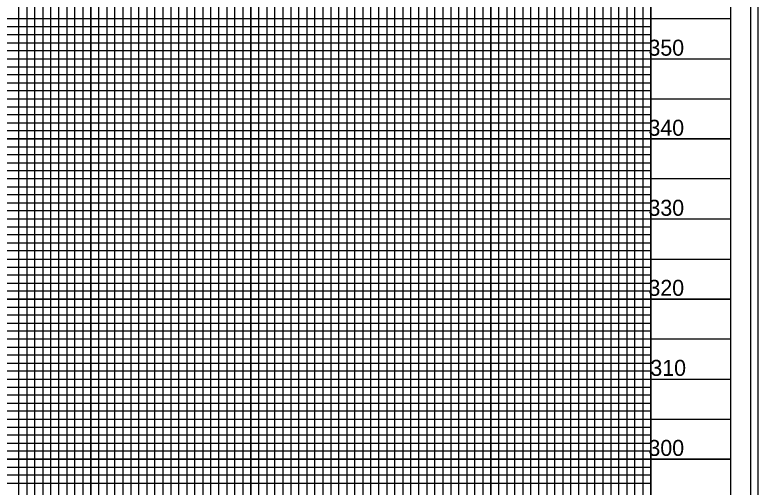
# Model space of a CAD drawing. Extents: x 10033 to 11717, y 9950 to 11050.
# Drawn here: x 11252.5 to 11717, y 10532.5 to 10827.5 of the extents above; entities that cross this region are included whole.
import ezdxf

# ---------------------------------------------------------------- set-up
doc = ezdxf.new("R2010")
doc.units = 0
for name, color, linetype in [('Exist Vertical Profile Vertical Axis Label', 7, 'Continuous'), ('Sheet DOT Grid CELL', 7, 'Continuous'), ('Sheet Layout Profile Border', 7, 'Continuous'), ('Sheet Plot Border Inside CELL', 7, 'Continuous'), ('Sheet Plot Border Outside CELL', 7, 'Continuous'), ('Sheet Profile CELL', 7, 'Continuous'), ('Sheet Profile Grid Major CELL', 7, 'Continuous'), ('Sheet Profile Grid Middle CELL', 7, 'Continuous'), ('Sheet Profile Grid Minor CELL', 7, 'Continuous')]:
    doc.layers.add(name, color=color, linetype=linetype)

msp = doc.modelspace()

# ---------------------------------------------------------------- linework, layer by layer
at = {"layer": 'Sheet DOT Grid CELL'}
for p, q in [((11300, 11025), (11300, 10000)), ((11350, 11025), (11350, 10000)), ((11400, 11025), (11400, 10000)), ((11450, 11025), (11450, 10000)), ((11500, 10000), (11500, 10887.45)), ((11550, 10000), (11550, 10887.45)), ((11600, 10000), (11600, 10887.45)), ((11650, 10000), (11650, 10887.45)), ((10200, 10800), (11700, 10800)), ((10200, 10750), (11700, 10750)), ((10200, 10700), (11700, 10700)), ((10200, 10650), (11700, 10650)), ((10200, 10600), (11700, 10600)), ((10200, 10550), (11700, 10550))]:
    msp.add_line(p, q, dxfattribs=at)
at = {"layer": 'Sheet Layout Profile Border'}
msp.add_lwpolyline([(10250, 11025), (10250, 10000), (11650, 10000), (11650, 10887.45), (11499.95, 10887.45), (11499.95, 11025)], close=True, dxfattribs=at)
at = {"layer": 'Sheet Plot Border Inside CELL'}
msp.add_lwpolyline([(11712.5, 11027.55), (10046, 11027.55), (10046, 9972.45), (11712.5, 9972.45)], close=True, dxfattribs=at)
at = {"layer": 'Sheet Plot Border Outside CELL'}
msp.add_lwpolyline([(11717, 11050), (10033, 11050), (10033, 9950), (11717, 9950)], close=True, dxfattribs=at)
at = {"layer": 'Sheet Profile CELL'}
msp.add_lwpolyline([(11700, 11025), (10200, 11025), (10200, 9975), (11700, 9975)], close=True, dxfattribs=at)
at = {"layer": 'Sheet Profile Grid Major CELL'}
for points in [[(11300, 10000), (11300, 11025), (11350, 11025), (11350, 10000)], [(11400, 10000), (11400, 11025), (11450, 11025), (11450, 10000)], [(11500, 10000), (11500, 11025), (11526.3, 11025)], [(11550, 10887.45), (11550, 10000), (11600, 10000), (11600, 10887.45)], [(11650, 10887.45), (11650, 10000), (11700, 10000)], [(11700, 10750), (10200, 10750), (10200, 10800), (11700, 10800)], [(11700, 10650), (10200, 10650), (10200, 10700), (11700, 10700)], [(11700, 10550), (10200, 10550), (10200, 10600), (11700, 10600)]]:
    msp.add_lwpolyline(points, dxfattribs=at)
at = {"layer": 'Sheet Profile Grid Middle CELL'}
for points in [[(11275, 10000), (11275, 11025), (11325, 11025), (11325, 10000)], [(11375, 10000), (11375, 11025), (11425, 11025), (11425, 10000)], [(11475, 10000), (11475, 11025)], [(11525, 10887.45), (11525, 10000), (11575, 10000), (11575, 10887.45)], [(11625, 10887.45), (11625, 10000)], [(11700, 10825), (10200, 10825), (10200, 10775), (11700, 10775)], [(11700, 10725), (10200, 10725), (10200, 10675), (11700, 10675)], [(11700, 10625), (10200, 10625), (10200, 10575), (11700, 10575)]]:
    msp.add_lwpolyline(points, dxfattribs=at)
at = {"layer": 'Sheet Profile Grid Minor CELL'}
msp.add_line((11650, 10820), (10250, 10820), dxfattribs=at)
for points in [[(11255, 10000), (11255, 11025), (11260, 11025), (11260, 10000)], [(11265, 10000), (11265, 11025), (11270, 11025), (11270, 10000)], [(11280, 10000), (11280, 11025), (11285, 11025), (11285, 10000)], [(11290, 10000), (11290, 11025), (11295, 11025), (11295, 10000)], [(11305, 10000), (11305, 11025), (11310, 11025), (11310, 10000)], [(11315, 10000), (11315, 11025), (11320, 11025), (11320, 10000)], [(11330, 10000), (11330, 11025), (11335, 11025), (11335, 10000)], [(11340, 10000), (11340, 11025), (11345, 11025), (11345, 10000)], [(11355, 10000), (11355, 11025), (11360, 11025), (11360, 10000)], [(11365, 10000), (11365, 11025), (11370, 11025), (11370, 10000)], [(11380, 10000), (11380, 11025), (11385, 11025), (11385, 10000)], [(11390, 10000), (11390, 11025), (11395, 11025), (11395, 10000)], [(11405, 10000), (11405, 11025), (11410, 11025), (11410, 10000)], [(11415, 10000), (11415, 11025), (11420, 11025), (11420, 10000)], [(11430, 10000), (11430, 11025), (11435, 11025), (11435, 10000)], [(11440, 10000), (11440, 11025), (11445, 11025), (11445, 10000)], [(11455, 10000), (11455, 11025), (11460, 11025), (11460, 10000)], [(11465, 10000), (11465, 11025), (11470, 11025), (11470, 10000)], [(11480, 10000), (11480, 11025), (11485, 11025), (11485, 10000)], [(11490, 10000), (11490, 11025), (11495, 11025), (11495, 10000)], [(11505, 10000), (11505, 10887.45)], [(11510, 10887.45), (11510, 10000), (11515, 10000), (11515, 10887.45)], [(11520, 10887.45), (11520, 10000), (11530, 10000), (11530, 10887.45)], [(11535, 10887.45), (11535, 10000), (11540, 10000), (11540, 10887.45)], [(11545, 10887.45), (11545, 10000), (11555, 10000), (11555, 10887.45)], [(11560, 10887.45), (11560, 10000), (11565, 10000), (11565, 10887.45)], [(11570, 10887.45), (11570, 10000), (11580, 10000), (11580, 10887.45)], [(11585, 10887.45), (11585, 10000)], [(11585, 10000), (11590, 10000), (11590, 10887.45)], [(11595, 10887.45), (11595, 10000), (11605, 10000), (11605, 10887.45)], [(11610, 10887.45), (11610, 10000), (11615, 10000), (11615, 10887.45)], [(11620, 10887.45), (11620, 10000), (11630, 10000), (11630, 10887.45)], [(11635, 10887.45), (11635, 10000), (11640, 10000), (11640, 10887.45)], [(11645, 10887.45), (11645, 10000), (11655, 10000)], [(11650, 10815), (10250, 10815), (10250, 10810), (11650, 10810)], [(11650, 10805), (10250, 10805)], [(10250, 10795), (11650, 10795)], [(11650, 10790), (10250, 10790), (10250, 10785), (11650, 10785)], [(11650, 10780), (10250, 10780), (10250, 10770), (11650, 10770)], [(11650, 10765), (10250, 10765), (10250, 10760), (11650, 10760)], [(11650, 10755), (10250, 10755), (10250, 10745), (11650, 10745)], [(11650, 10740), (10250, 10740), (10250, 10735), (11650, 10735)], [(11650, 10730), (10250, 10730), (10250, 10720), (11650, 10720)], [(11650, 10715), (10250, 10715), (10250, 10710), (11650, 10710)], [(11650, 10705), (10250, 10705), (10250, 10695), (11650, 10695)], [(11650, 10690), (10250, 10690), (10250, 10685), (11650, 10685)], [(11650, 10680), (10250, 10680), (10250, 10670), (11650, 10670)], [(11650, 10665), (10250, 10665), (10250, 10660), (11650, 10660)], [(11650, 10655), (10250, 10655), (10250, 10645), (11650, 10645)], [(11650, 10640), (10250, 10640), (10250, 10635), (11650, 10635)], [(11650, 10630), (10250, 10630), (10250, 10620), (11650, 10620)], [(11650, 10615), (10250, 10615), (10250, 10610), (11650, 10610)], [(11650, 10605), (10250, 10605), (10250, 10595), (11650, 10595)], [(11650, 10590), (10250, 10590), (10250, 10585), (11650, 10585)], [(11650, 10580), (10250, 10580), (10250, 10570), (11650, 10570)], [(11650, 10565), (10250, 10565), (10250, 10560), (11650, 10560)], [(11650, 10555), (10250, 10555), (10250, 10545), (11650, 10545)], [(11650, 10540), (10250, 10540), (10250, 10535), (11650, 10535)]]:
    msp.add_lwpolyline(points, dxfattribs=at)

# ---------------------------------------------------------------- texts
at = {"layer": 'Exist Vertical Profile Vertical Axis Label'}
for s, p in [('350', (11648.43, 10802)), ('340', (11648.43, 10752)), ('330', (11648.43, 10702)), ('320', (11648.43, 10652)), ('310', (11649.63, 10602)), ('300', (11648.43, 10552))]:
    msp.add_text(s, height=10, dxfattribs=at).set_placement(p)

doc.saveas('drawing.dxf')
